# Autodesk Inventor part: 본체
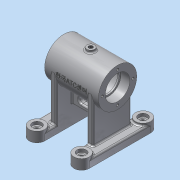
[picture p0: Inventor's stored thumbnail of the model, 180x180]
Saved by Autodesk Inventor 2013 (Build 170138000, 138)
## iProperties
Created: 2015-11
Part Number: 본체
Material: 알루미늄 6061
Document SubType Name: Modeling
Designer: User11
Density: 2.71 g/cm^3
Mass: 357.638 g
Surface Area: 467.122 cm^2
Volume: 131.97 cm^3
Author: User11
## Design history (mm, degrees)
sketch "스케치2"
  geometry: L1 (0, 0)-(70, 0); L2 (0, 25)-(70, 25); L3 (70, 25)-(70, 16); L4 (70, 16)-(58, 16); L5 (58, 16)-(58, 14); L6 (58, 14)-(56, 14); L7 (56, 14)-(56, 21); L8 (56, 21)-(14, 21); L9 (14, 21)-(14, 14); L10 (14, 14)-(12, 14); L11 (12, 14)-(12, 16); L12 (12, 16)-(0, 16); L13 (0, 16)-(0, 25)
  constraints: 26 end point, 6 parallel, 6 perpendicular, 1 horizontal
  dimensions: "d0" = 70 distance of L1.start L1.end; "d1" = 0 distance from line of L13 L1.start; "d2" = 70 distance between parallel lines of L13 L3; "d3" = 42 diameter of L8 L1; "d4" = 50 diameter of L2 L1; "d5" = 32 diameter of L4 L1; "d7" = 28 diameter of L6 L1; "d9" = 28 diameter of L10 L1; "d10" = 32 diameter of L12 L1; "d11" = 12 distance of L3.end L4.end; "d12" = 12 distance of L11.end L12.end; "d13" = 2 distance of L5.end L6.end; "d14" = 2 distance of L9.end L10.end
revolve "회전1" sketch "스케치2" stored, may be unused: angle "d15" = 90 deg
fillet "모깎기1" dims "d16" = 0.3
sketch "스케치3"
  geometry: L1 (0, 0)-(0, 20); L2 (0, 0)-(0, -20); L3 (0, 0)-(-20, 0); L4 (0, 0)-(20, 0); C1 r 25 at (0, 0) reference; A1 r 20 centre (0, 0) between (0, 20) and (0, -20); 4 further points
  constraints: 8 end point, 5 coincident, 4 point on circle, 2 collinear, 1 centre point, 1 perpendicular, 1 vertical
  dimensions: "d17" = 40 diameter of A1
hole "구멍1" sketch "스케치3" at (0, -20), (-20, 0), (0, 20), (20, 0) diameter "d19" = 3.242; stored, may be unused: countersink angle "d23" = 90 deg, drill point angle "d25" = 118 deg; dims "d20" = 8, "d21" = 4, "d22" = 2, "d24" = 10
sketch "스케치4"
  geometry: C1 r 16 at (0, 0) reference; C2 r 20 at (0, 0); C3 r 21 at (0, 0) reference; C4 r 1.621 at (0, 20) reference; C5 r 1.621 at (-20, 0) reference; C6 r 1.621 at (0, -20) reference; C7 r 1.621 at (20, 0) reference; 4 further points
  constraints: 5 coincident, 1 centre point
  dimensions: "d26" = 40 diameter of C2
hole "구멍2" sketch "스케치4" at (20, 0), (0, -20), (-20, 0), (0, 20) diameter "d28" = 3.242; stored, may be unused: countersink angle "d32" = 90 deg, drill point angle "d34" = 118 deg; dims "d29" = 8, "d30" = 4, "d31" = 2, "d33" = 10
fillet "모깎기2" dims "d35" = 3
node "작업 평면1"
sketch "스케치5"
  geometry: L1 (70, -25)-(70, 25) reference; L2 (0, -25)-(0, 25) reference; L3 (70, 0)-(0, 0); L4 (0, 25)-(70, 25) reference; L5 (35, 25)-(35, 0); C1 r 5 at (35, 0)
  constraints: 4 end point, 3 midpoint, 1 centre point, 1 coincident, 1 perpendicular
  dimensions: "d37" = 10 diameter of C1
extrude "돌출1" join sketch "스케치5" stored distance "d39" = 10; taper "d40" = 0 deg
sketch "스케치6"
  geometry: C1 r 5 at (0, 0) reference; 1 further point
hole "구멍3" sketch "스케치6" at (0, 0) diameter "d41" = 5.188; stored, may be unused: countersink angle "d45" = 90 deg, drill point angle "d47" = 118 deg; dims "d42" = 8, "d43" = 4, "d44" = 2, "d46" = 10
node "작업 평면6"
sketch "스케치7"
  geometry: L1 (55, -41.857)-(55, 38.143); L2 (75, -41.857)-(75, 38.143); L3 (65, -41.857)-(55, -41.857); L4 (65, 38.143)-(55, 38.143); L5 (0, -25)-(0, 25) reference; L6 (0, -25)-(0, 25) reference; L7 (70, -25)-(70, 25) reference; L8 (55, -1.857)-(75, -1.857); L9 (35, 5)-(35, -5); A1 r 10 centre (65, -41.857) between (55, -41.857) and (75, -41.857); A2 r 10 centre (65, 38.143) between (75, 38.143) and (55, 38.143); A3 r 10 centre (65, 38.143) between (55, 38.143) and (75, 38.143); A4 r 10 centre (65, -41.857) between (75, -41.857) and (55, -41.857); 1 further point
  constraints: 12 end point, 8 point on circle, 5 tangent, 4 centre point, 2 midpoint, 2 parallel, 2 perpendicular, 1 vertical, 1 vertical alignment, 1 other
  dimensions: "d53" = 20 diameter of A1; "d55" = 20 diameter of A2; "d56" = 80 distance between parallel lines of L4 L3; "d58" = 30 distance from line of L3.start L9
  node "투영된 루프2"
extrude "돌출2" join sketch "스케치7" distance "d59" = 13; taper "d60" = 0 deg
extrude "돌출3" join sketch "스케치7" distance "d61" = 10; taper "d62" = 0 deg
sketch "스케치8"
  geometry: C1 r 10 at (0, 0) reference; C2 r 6 at (0, 0); 1 further point
  constraints: 1 centre point, 1 coincident
  dimensions: "d63" = 12 diameter of C2
sketch "스케치9"
  geometry: C1 r 10 at (0, 0) reference; C2 r 6 at (0, 0); 1 further point
  constraints: 1 centre point, 1 coincident
  dimensions: "d65" = 12 diameter of C2
extrude "돌출4" cut sketch "스케치8" distance "d67" = 4; taper "d68" = 0 deg
extrude "돌출5" cut sketch "스케치9" distance "d69" = 4; taper "d70" = 0 deg
sketch "스케치10"
  geometry: C1 r 6 at (0, 0) reference; C2 r 3 at (0, 0); 1 further point
  constraints: 1 centre point, 1 coincident
  dimensions: "d71" = 6 diameter of C2
sketch "스케치11"
  geometry: C1 r 6 at (0, 0) reference; C2 r 3 at (0, 0); 1 further point
  constraints: 1 centre point, 1 coincident
  dimensions: "d73" = 6 diameter of C2
extrude "돌출6" cut sketch "스케치10" stored distance "d75" = 4; taper "d76" = 0 deg
extrude "돌출7" cut sketch "스케치11" stored distance "d77" = 4; taper "d78" = 0 deg
fillet "모깎기3" dims "d79" = 0.3
chamfer "모따기1" distance "d80" = 1; stored, may be unused: second distance "d81" = 2, angle "d82" = 45 deg
chamfer "모따기2" distance "d83" = 1; stored, may be unused: second distance "d84" = 2, angle "d85" = 45 deg
sketch "스케치12"
  geometry: L1 (55, 38.143)-(55, -41.857) reference; L2 (55, -25)-(63, -25); L3 (63, -25)-(63, 25); L4 (63, 25)-(55, 25); 1 further point
  constraints: 6 end point, 3 perpendicular, 2 point on line
  dimensions: "d86" = 50 distance of L2.end L3.end; "d88" = 8 distance between parallel lines of L1 L3; "d89" = 25 distance from line of L2 point (0, 0)
extrude "돌출9" join sketch "스케치12" stored distance "d92" = 4; taper "d93" = 0 deg
node "작업 평면7"
sketch "스케치14"
  geometry: L1 (-5, 40)-(-5, -40); L2 (15, 40)-(15, -40); L3 (5, 40)-(5, -40); L4 (5, 40)-(15, 40); L5 (15, 0)-(-5, 0); C1 r 5 at (35, 0) reference; A1 r 10 centre (5, 40) between (-5, 40) and (15, 40); A2 r 10 centre (5, -40) between (-5, -40) and (15, -40); 1 further point
  constraints: 10 end point, 4 point on circle, 3 tangent, 2 centre point, 2 midpoint, 1 parallel, 1 perpendicular, 1 vertical
  dimensions: "d95" = 20 diameter of A1; "d97" = 20 diameter of A2; "d98" = 80 distance of L3.start L3.end; "d99" = 40 distance from line of L4 point (0, 0); "d100" = 30 distance from line of L3 C1.centre
extrude "돌출10" join sketch "스케치14" distance "d101" = 13; taper "d102" = 0 deg
extrude "돌출11" join sketch "스케치14" distance "d103" = 10; taper "d104" = 0 deg
sketch "스케치15"
  geometry: C1 r 10 at (0, 0) reference; C2 r 6 at (0, 0); 1 further point
  constraints: 1 centre point, 1 coincident
  dimensions: "d105" = 12 diameter of C2
sketch "스케치16"
  geometry: C1 r 10 at (0, 0) reference; C2 r 6 at (0, 0); 1 further point
  constraints: 1 centre point, 1 coincident
  dimensions: "d107" = 12 diameter of C2
extrude "돌출12" cut sketch "스케치15" distance "d109" = 4; taper "d110" = 0 deg
extrude "돌출13" cut sketch "스케치16" distance "d111" = 4; taper "d112" = 0 deg
sketch "스케치17"
  geometry: C1 r 6 at (0, 0) reference; C2 r 3 at (0, 0); 1 further point
  constraints: 1 centre point, 1 coincident
  dimensions: "d113" = 6 diameter of C2
sketch "스케치18"
  geometry: C1 r 6 at (0, 0) reference; C2 r 3 at (0, 0); 1 further point
  constraints: 1 centre point, 1 coincident
  dimensions: "d115" = 6 diameter of C2
extrude "돌출14" cut sketch "스케치17" stored distance "d117" = 4; taper "d118" = 0 deg
extrude "돌출15" cut sketch "스케치18" stored distance "d119" = 4; taper "d120" = 0 deg
chamfer "모따기3" distance "d121" = 1; stored, may be unused: second distance "d122" = 2, angle "d123" = 45 deg
chamfer "모따기4" distance "d124" = 1; stored, may be unused: second distance "d125" = 2, angle "d126" = 45 deg
sketch "스케치19"
  geometry: L1 (15, -40)-(15, 40) reference; L2 (15, 25)-(7, 25); L3 (7, 25)-(7, -25); L4 (7, -25)-(15, -25); 1 further point
  constraints: 6 end point, 2 perpendicular, 2 point on line, 1 parallel
  dimensions: "d127" = 8 distance of L2.start L2.end; "d129" = 25 distance from line of point (0, 0) L2; "d130" = 50 distance of L2.end L3.end
extrude "돌출16" join sketch "스케치19" stored distance "d131" = 4; taper "d132" = 0 deg
fillet "모깎기4" dims "d133" = 2
sketch "스케치20"
  geometry: L1 (-15, -58)-(-15, -9.798) reference; L2 (0, -25)-(-70, -25) reference; L3 (-55, -9.798)-(-55, -58) reference; L4 (-15, -45)-(-55, -45); L5 (-55, -45)-(-55, -25); L6 (-55, -25)-(-15, -25); L7 (-15, -25)-(-15, -45); L8 (-27, -31.5)-(-43, -31.5); L9 (-43, -38.5)-(-27, -38.5); L10 (-23.5, -35)-(-46.5, -35); L11 (-35, -45)-(-35, -25); L12 (5, -68)-(-15, -68) reference; A1 r 3.5 centre (-43, -35) between (-43, -31.5) and (-43, -38.5); A2 r 3.5 centre (-27, -35) between (-27, -38.5) and (-27, -31.5); 3 further points
  constraints: 16 end point, 6 point on circle, 3 parallel, 3 point on line, 3 tangent, 2 centre point, 2 midpoint, 2 perpendicular, 1 horizontal
  dimensions: "d135" = 20 distance of L6.end L4.start; "d138" = 23 distance of L10.start L10.end; "d139" = 3.5 radius of A1; "d140" = 11.5 distance from line of L10.start L11; "d141" = 33 distance between parallel lines of L12 L10
extrude "돌출17" join sketch "스케치20" stored distance "d142" = 8; taper "d143" = 0 deg
fillet "모깎기6" dims "d144" = 2
fillet "모깎기7" dims "d145" = 2
node "작업 평면8"
sketch "스케치21"
  geometry: L1 (21.079, 1.97)-(48.921, 1.97); L2 (48.921, 1.97)-(48.921, -1.97); L3 (48.921, -1.97)-(21.079, -1.97); L4 (21.079, -1.97)-(21.079, 1.97); L5 (21.079, 0)-(48.921, 0); L6 (35, 1.97)-(35, -1.97); L7 (0, -25)-(0, 25) reference; L8 (0, 25)-(70, 25) reference; 1 further point
  constraints: 4 end point, 4 midpoint, 1 parallel, 2 other
  dimensions: "d147" = 35 distance between parallel lines of L7 L6; "d149" = 25 distance between parallel lines of L5 L8
feature "엠보싱1" sketch "스케치21" dims "d150" = 0.5, "d151" = 0
fillet "모깎기8" dims "d152" = 2
fillet "모깎기9" dims "d153" = 2
fillet "모깎기10" dims "d154" = 2
node "솔리드1"
node "투영된 루프1"
other parameters: "d36" = 28, "d52" = -68, "d94" = -68, "d146" = -83.75
